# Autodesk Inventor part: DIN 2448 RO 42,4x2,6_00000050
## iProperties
Created: 2006-03
Part Number: DIN 2448 RO 42,4x2,6_00000050
Material: Default
Document SubType Name: Modeling
Designer: Carlo
Stock Number: DIN 2448 RO 42,4x2,6
Mass: 507.137 g
Surface Area: 3914.3 cm^2
Volume: 507.137 cm^3
Density: 1 g/cm^3
G_L: 1590.000 mm
G_W: 42.400 mm
G_H: 42.400 mm
AFG_Item: 42.4 x 2.6
CSToolsMass: 1.0
CSToolsVolume: 507137.0
CSToolsArea: 3914.0
Author: Carlo
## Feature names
1. AFG_Detailed_DIN 2448 RO 42,4x2,6_00000050 [Extrusion]
2. AFG_Simplified_DIN 2448 RO 42,4x2,6_00000050 [Extrusion]
3. AFG_StartExtrusion_1 [Extrusion]
4. AFG_StartExtrusion_2 [Extrusion]
5. AFG_EndExtrusion_1 [Extrusion]
6. AFG_EndExtrusion_2 [Extrusion]
